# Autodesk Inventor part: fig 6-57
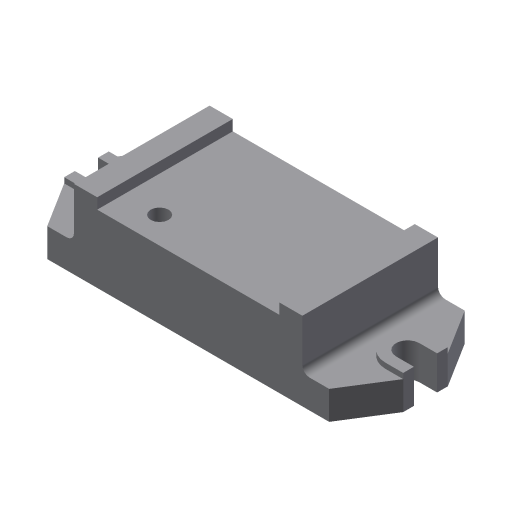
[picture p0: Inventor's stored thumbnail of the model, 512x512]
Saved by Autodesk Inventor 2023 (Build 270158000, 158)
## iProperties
Created: 2001-12
Part Number: fig 6-57
Document SubType Name: Modeling
Designer: Renu Muthoo
Density: 1 g/cm^3
Material: Generic
Appearance: Default
Control State: 0
Master: False
Checked Out: False
Shininess: 77.0
Angle Display Precision: 2
Document Length Units: 11269
Document Angle Units: 11279
Document Time Units: 11290
Document Mass Units: 11283
Document Length Units Precision: 3
Document Angle Units Precision: 2
Density: 0.0
Volumn: 0.0
Area: 0.0
PropertySet Name: Model Information
Author: Renu Muthoo
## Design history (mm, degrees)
sketch "Sketch3"
  geometry: L1 (-59.119, -24.322)-(-59.119, 19.678); L2 (-59.119, 19.678)-(-46.119, 19.678); L3 (-46.119, 19.678)-(-46.119, 13.678); L4 (-46.119, 13.678)-(55.881, 13.678); L5 (55.881, 13.678)-(55.881, 19.678); L6 (55.881, 19.678)-(68.881, 19.678); L7 (68.881, 19.678)-(68.881, -24.322); L8 (68.881, -24.322)-(-59.119, -24.322)
  constraints: 16 end point, 2 equal length
  dimensions: "d10" = 13 distance of L1.end L2.end; "d11" = 102 distance of L3.end L4.end; "d13" = 44 distance between parallel lines of L2 L8; "d14" = 6 distance of L2.end L3.end
extrude "Extrusion1" new body sketch "Sketch3" distance "d15" = 76; taper "d16" = 0 deg
sketch "Sketch4"
  geometry: L1 (0, 0)-(0, 76) reference; L2 (0, 76)-(-15, 76); L3 (-15, 76)-(-31, 50.5); L4 (-31, 50.5)-(-31, 44.5); L5 (-31, 44.5)-(-21, 44.5); L6 (-21, 31.5)-(-31, 31.5); L7 (-31, 31.5)-(-31, 25.5); L8 (-31, 25.5)-(-15, 0); L9 (-15, 0)-(0, 0); L10 (128, 76)-(0, 76) reference; L11 (0, 0)-(128, 0) reference; A1 r 6.5 centre (-21, 38) between (-21, 31.5) and (-21, 44.5)
  constraints: 16 end point, 4 equal length, 3 collinear, 3 parallel, 2 perpendicular, 2 point on circle, 2 tangent, 1 centre point
  dimensions: "d17" = 13 distance between parallel lines of L6 L5; "d18" = 25 distance of L3.end L7.end; "d19" = 10 distance of L6.start L6.end; "d20" = 15 distance of L8.end L1.start; "d21" = 16 horizontal distance of L7.end L8.end
extrude "Extrusion2" join sketch "Sketch4" distance "d22" = 16; taper "d23" = 0 deg
sketch "Sketch5"
  geometry: L1 (-159, 44.5)-(-159, 50.5) reference; L2 (-149, 44.5)-(-159, 44.5) reference; L3 (-159, 31.5)-(-149, 31.5) reference; L4 (-159, 25.5)-(-159, 31.5) reference; L5 (-159, 25.5)-(-149, 25.5); L6 (-149, 50.5)-(-159, 50.5); A1 r 6.5 centre (-149, 38) between (-149, 31.5) and (-149, 44.5) reference; A2 r 12.5 centre (-149, 38) between (-149, 25.5) and (-149, 50.5)
  constraints: 4 end point, 2 point on circle, 2 tangent, 1 centre point, 1 parallel, 1 perpendicular
extrude "Extrusion3" join sketch "Sketch5" distance "d24" = 19; taper "d25" = 0 deg
workplane "Work Plane1"
mirror "Mirror1"
fillet "Fillet1" dims "d27" = 4
sketch "Sketch6"
  geometry: L1 (0, 0)-(0, 76) reference; L2 (0, 0)-(102, 0) reference; 1 further point
  dimensions: "d28" = 20 distance from line of L1 point (20, 15); "d29" = 15 distance from line of L2 point (20, 15)
hole "Hole1" sketch "Sketch6" at (20, 15) diameter "d30" = 10; stored, may be unused: countersink angle "d34" = 82 deg, drill point angle "d36" = 118 deg; dims "d31" = 6, "d32" = 4, "d33" = 2, "d35" = 15
sketch "Sketch7"
  geometry: C1 r 5 at (20, 15) reference; 3 further points
  constraints: 4 other
body "Solid1"
other parameters: "d26" = -64
